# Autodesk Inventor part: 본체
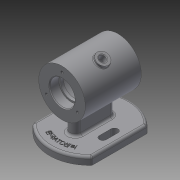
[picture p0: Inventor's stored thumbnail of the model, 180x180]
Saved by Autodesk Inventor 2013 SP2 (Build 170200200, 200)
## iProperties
Created: 2022-02
Part Number: 본체
Material: Generic
Document SubType Name: Modeling
Designer: a
Density: 1 g/cm^3
Author: a
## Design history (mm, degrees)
sketch "스케치1"
  geometry: L1 (-36, 0)-(36, 0); L2 (-36, 0)-(-36, 30); L3 (-36, 30)-(36, 30); L4 (36, 30)-(36, 0); L5 (-24, 16)-(-24, 14); L6 (-24, 14)-(-20, 14); L7 (-20, 14)-(-20, 25); L8 (-20, 25)-(20, 25); L9 (20, 25)-(20, 14); L10 (20, 14)-(24, 14); L11 (24, 14)-(24, 16); L12 (24, 16)-(36, 16); L13 (-24, 16)-(-36, 16); 2 further points
  constraints: 26 end point, 4 parallel, 3 perpendicular, 2 point on line, 1 coincident, 1 collinear, 1 horizontal, 1 midpoint, 1 vertical
  dimensions: "d0" = 72 distance of L1.start L1.end; "d1" = 60 diameter of L3 L1; "d2" = 50 diameter of L8 L1; "d3" = 32 diameter of L12 L1; "d4" = 28 diameter of L10 L1; "d5" = 28 diameter of L6 L1; "d6" = 32 diameter of L13 L1; "d7" = 12 distance of L5.start L13.end; "d8" = 40 distance of L8.end L7.end; "d9" = 4 distance of L6.end L5.end; "d10" = 4 distance of L10.end L9.end
revolve "회전1" sketch "스케치1" stored, may be unused: angle "d11" = 90 deg
node "작업 평면1"
sketch "스케치2"
  geometry: L1 (-35.496, 38)-(35.496, 38); L2 (35.496, 38)-(35.496, -38); L3 (35.496, -38)-(-35.496, -38); L4 (-35.496, -38)-(-35.496, 38); L5 (-35.496, 38)-(35.496, -38); L6 (35.496, 38)-(-35.496, -38); A1 r 52 centre (0, 0) between (-35.496, 38) and (-35.496, -38); A2 r 52 centre (0, 0) between (35.496, -38) and (35.496, 38); 1 further point
  constraints: 12 end point, 4 point on circle, 2 centre point, 2 midpoint, 2 parallel, 1 coincident, 1 horizontal, 1 perpendicular
  dimensions: "d14" = 76 distance of L1.end L2.end; "d15" = 52 radius of A1
extrude "돌출1" join sketch "스케치2" distance "d16" = 10; taper "d17" = 0 deg
sketch "스케치3"
  geometry: L1 (-19, 7)-(19, 7); L2 (19, 7)-(19, -7); L3 (19, -7)-(-19, -7); L4 (-19, -7)-(-19, 7); L5 (-19, 7)-(19, -7); L6 (19, 7)-(-19, -7); L7 (-7.5, 28.5)-(7.5, 28.5); L8 (7.5, 28.5)-(7.5, 19.5); L9 (7.5, 19.5)-(-7.5, 19.5); L10 (-7.5, 19.5)-(-7.5, 28.5); L11 (-7.5, 28.5)-(7.5, 19.5); L12 (7.5, 28.5)-(-7.5, 19.5); L13 (-7.5, -19.5)-(7.5, -19.5); L14 (7.5, -19.5)-(7.5, -28.5); L15 (7.5, -28.5)-(-7.5, -28.5); L16 (-7.5, -28.5)-(-7.5, -19.5); L17 (-7.5, -19.5)-(7.5, -28.5); L18 (7.5, -19.5)-(-7.5, -28.5); A1 r 52 centre (0, 0) between (35.496, -38) and (35.496, 38) reference; A2 r 52 centre (0, 0) between (-35.496, 38) and (-35.496, -38) reference; 12 further points
  constraints: 36 end point, 16 midpoint, 8 vertical alignment, 6 parallel, 3 horizontal, 3 perpendicular, 12 other
  dimensions: "d18" = 38 distance of L2.end L3.end; "d19" = 14 distance of L1.end L2.end; "d20" = 15 distance of L8.end L9.end; "d21" = 9 distance of L7.end L8.end; "d22" = 15 distance of L14.end L15.end; "d23" = 9 distance of L13.end L14.end; "d24" = 24 distance of point (0, 24) A2.centre; "d25" = 24 distance of point (0, -24) A1.centre
extrude "돌출2" cut sketch "스케치3" distance "d26" = 10; taper "d27" = 0 deg
extrude "돌출3" join sketch "스케치3" stored distance "d28" = 10; taper "d29" = 0 deg
sketch "스케치4" dims "d30" = 46
  geometry: C1 r 16 at (0, 0) reference; 2 further points
  constraints: 2 vertical alignment, 1 coincident, 2 other
hole "구멍1" sketch "스케치4" at (0, 23) diameter "d31" = 3.242; stored, may be unused: countersink angle "d35" = 82 deg, drill point angle "d37" = 118 deg; dims "d32" = 8, "d33" = 3.023, "d34" = 2, "d36" = 10
sketch "스케치5"
  geometry: L1 (0, 0)-(30, 0); L2 (0, 0)-(28.579, 16.5); 1 further point
  constraints: 4 end point, 1 horizontal, 1 horizontal alignment, 1 other
  dimensions: "d41" = 33 distance of L1.start L2.end; "d42" = 30 deg angle of L1 L2
node "작업 평면2"
sketch "스케치6"
  geometry: C1 r 8 at (0, 0); 1 further point
  constraints: 1 centre point, 1 coincident
  dimensions: "d43" = 16 diameter of C1
extrude "돌출4" join sketch "스케치6" stored distance "d44" = 10; taper "d45" = 0 deg
sketch "스케치7"
  geometry: C1 r 8 at (0, 0) reference; C2 r 4 at (0, 0)
  constraints: 1 centre point, 1 coincident
  dimensions: "d46" = 8 diameter of C2
extrude "돌출5" cut sketch "스케치7" stored distance "d47" = 10; taper "d48" = 0 deg
sketch "스케치8"
  geometry: C1 r 42.5 at (0, 0); A1 r 52 centre (0, 0) between (35.496, -38) and (35.496, 38) reference
  constraints: 1 centre point, 1 coincident, 1 other
  dimensions: "d49" = 85 diameter of C1
feature "엠보싱1" sketch "스케치8" dims "d14" = 76, "d15" = 52, "d50" = 0.5, "d51" = 0
fillet "모깎기1" dims "d52" = 3
fillet "모깎기2" dims "d53" = 3
fillet "모깎기3" dims "d54" = 3
fillet "모깎기4" dims "d55" = 1
chamfer "모따기1" distance "d56" = 1; stored, may be unused: second distance "d57" = 2, angle "d58" = 45 deg
fillet "모깎기5" dims "d59" = 0.3
fillet "모깎기6" dims "d60" = 3
node "솔리드1"
pattern_circular "원형 패턴1" dims angle "d39" = 360 deg
mirror "대칭1"
other parameters: "d12" = -62, "d13" = 104
